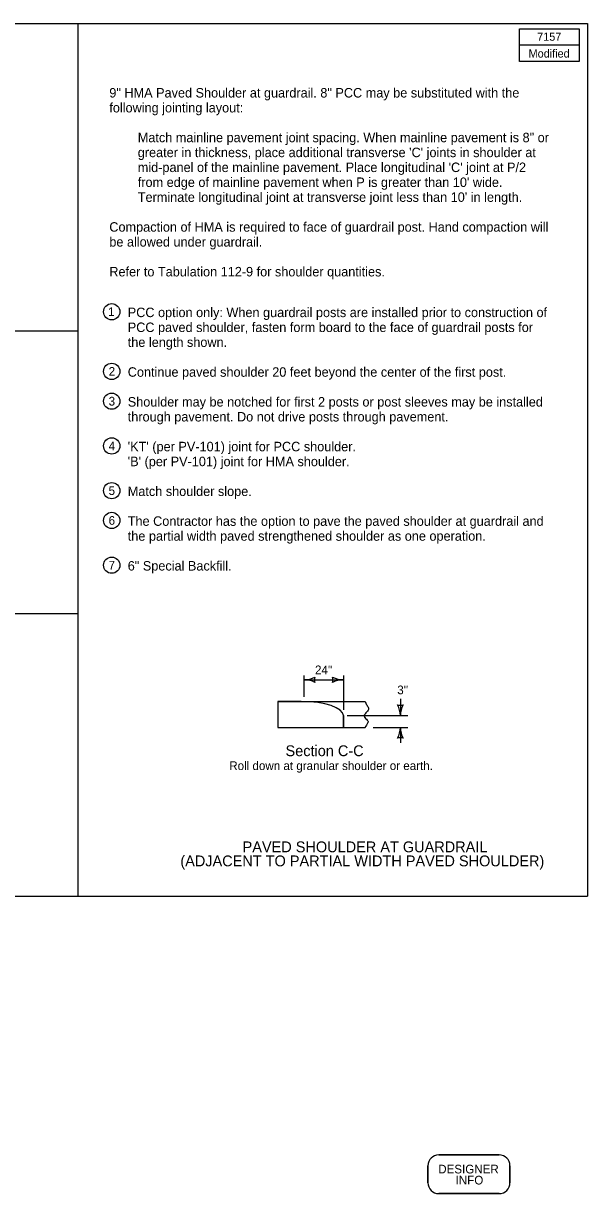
# Model space of a CAD drawing. Extents: x 10133 to 81668, y 7924 to 12229.
# Drawn here: x 12201 to 13243, y 10071 to 12229 of the extents above; entities that cross this region are included whole.
import ezdxf

# ---------------------------------------------------------------- set-up
doc = ezdxf.new("R2010")
doc.units = 0
for name, color, linetype in [('Cell', 7, 'Continuous'), ('dsnStdCells', 7, 'Continuous'), ('dsnTextFinalPlan', 7, 'Continuous'), ('Level 1', 7, 'Continuous'), ('Level 12', 7, 'Continuous'), ('Level 4', 7, 'Continuous'), ('Level 5', 7, 'Continuous'), ('Level 6', 7, 'Continuous'), ('SheetText', 7, 'Continuous')]:
    doc.layers.add(name, color=color, linetype=linetype)

msp = doc.modelspace()

# ---------------------------------------------------------------- linework, layer by layer
at = {"layer": 'Cell'}
for p, q in [((12714.3, 10978.5), (12671.2, 10978.5)), ((12671.2, 10978.5), (12671.2, 10930.5)), ((12792.1, 10930.5), (12792.1, 10952.3)), ((12671.2, 10930.5), (12792.1, 10930.5))]:
    msp.add_line(p, q, dxfattribs=at)
msp.add_lwpolyline([(12714.3, 10978.4), (12714.3, 10978.5)], dxfattribs=at)
msp.add_ellipse((12714.3, 10952.3), major_axis=(77.9, 0), ratio=0.335273, start_param=0, end_param=1.570796, dxfattribs=at)
at = {"layer": 'dsnStdCells'}
for points in [[(12968.1, 10142), (13079.5, 10142)], [(13079.5, 10142), (12968.1, 10142)], [(12948.1, 10090.6), (12948.1, 10122)], [(12948.1, 10122), (12948.1, 10090.6)], [(13099.5, 10122), (13099.5, 10090.6)], [(13099.5, 10090.6), (13099.5, 10122)], [(13079.5, 10070.6), (12968.1, 10070.6)], [(12968.1, 10070.6), (13079.5, 10070.6)]]:
    msp.add_lwpolyline(points, dxfattribs=at)
for centre, start, end in [((12968.1, 10122), 90, 180), ((12968.1, 10122), 90, 180), ((13079.5, 10122), 0, 90), ((13079.5, 10122), 0, 90), ((12968.1, 10090.6), 180, 270), ((12968.1, 10090.6), 180, 270), ((13079.5, 10090.6), 270, 0), ((13079.5, 10090.6), 270, 0)]:
    msp.add_arc(centre, 20, start, end, dxfattribs=at)
at = {"layer": 'dsnTextFinalPlan'}
for p, q in [((13242.8, 12229.2), (13242.8, 12229.2)), ((12671.2, 10978.5), (12671.2, 10930.5)), ((12671.2, 10978.5), (12714.3, 10978.4)), ((12714.3, 10978.4), (12832, 10978.4)), ((12792.1, 10952.3), (12792.1, 10930.5)), ((12671.2, 10930.5), (12792.1, 10930.5)), ((12792.1, 10930.5), (12832, 10930.5))]:
    msp.add_line(p, q, dxfattribs=at)
msp.add_ellipse((12714.3, 10952.3), major_axis=(77.9, 0), ratio=0.335273, start_param=0, end_param=1.570796, dxfattribs=at)
msp.add_spline([(12832, 10978.4), (12833.4, 10975.3), (12835.2, 10972.1), (12837.1, 10969.1), (12838.5, 10966), (12838.7, 10964.2), (12838, 10962.5), (12835.1, 10959), (12832, 10955.5), (12830.9, 10953.8), (12830.5, 10952.9), (12830.4, 10952), (12830.4, 10951.6), (12830.8, 10950.4), (12831.8, 10948.8), (12834.7, 10945.6), (12837.2, 10942.5), (12837.7, 10940.9), (12837.6, 10940.1), (12837.4, 10939.7), (12837.2, 10939.3), (12831.9, 10930.5)], degree=3, dxfattribs=at)
at = {"layer": 'Level 1'}
for p, q in [((10147.1, 12229.2), (13242.8, 12229.2)), ((13242.8, 12229.2), (13242.8, 10619.2)), ((10147.1, 10619.2), (13242.8, 10619.2))]:
    msp.add_line(p, q, dxfattribs=at)
at = {"layer": 'Level 12'}
for centre in [(12364.5, 11697.3), (12364.5, 11587.3), (12364.5, 11532.3), (12364.5, 11449.8), (12364.5, 11367.3), (12364.5, 11312.3), (12364.5, 11229.8)]:
    msp.add_circle(centre, 15, dxfattribs=at)
at = {"layer": 'Level 4'}
for p, q in [((12302.7, 10619.2), (12302.7, 12229.2)), ((12302.7, 11661.2), (10147.1, 11661.2)), ((12302.7, 11140.2), (10147.1, 11140.2))]:
    msp.add_line(p, q, dxfattribs=at)
at = {"layer": 'Level 5'}
for p, q in [((12719.6, 10987), (12719.6, 11026.4)), ((12719.6, 11018.4), (12792.1, 11018.4)), ((12792.1, 11026.4), (12792.1, 10962.9)), ((12897.2, 10983.3), (12897.2, 10952.3)), ((12798.9, 10952.3), (12911, 10952.3)), ((12846.9, 10930.5), (12911, 10930.5)), ((12897.2, 10930.5), (12897.2, 10901.9))]:
    msp.add_line(p, q, dxfattribs=at)
for centre, radius, start, end in [((12719.6, 11060.9), 42.5, 270, 298.0725), ((12719.6, 10975.9), 42.5, 61.9275, 90), ((12755.2, 11018.4), 16.4, 162.2666, 197.7334), ((12756.5, 11018.4), 16.4, 342.2666, 17.7334), ((12792.1, 11060.9), 42.5, 241.9275, 270), ((12792.1, 10975.9), 42.5, 90, 118.0725), ((12897.2, 10988), 16.4, 252.2666, 287.7334), ((12854.7, 10952.3), 42.5, 0, 28.0725), ((12939.7, 10952.3), 42.5, 151.9275, 180), ((12854.7, 10930.5), 42.5, 331.9275, 360), ((12939.7, 10930.5), 42.5, 180, 208.0725), ((12897.2, 10894.9), 16.4, 72.2666, 107.7334)]:
    msp.add_arc(centre, radius, start, end, dxfattribs=at)
at = {"layer": 'SheetText'}
msp.add_lwpolyline([(13227.1, 12219.2), (13227.1, 12159.2), (13117.1, 12159.2), (13117.1, 12219.2), (13227.1, 12219.2), (13227.1, 12189.2), (13117.1, 12189.2)], dxfattribs=at)

# ---------------------------------------------------------------- texts
at = {"layer": 'dsnStdCells'}
for s, p in [('DESIGNER', (12967.1, 10107.8)), ('INFO', (12999.2, 10087.4))]:
    msp.add_text(s, height=16, dxfattribs=at).set_placement(p)
at = {"layer": 'Level 12'}
for s, height, p in [('9" HMA Paved Shoulder at guardrail. 8" PCC may be substituted with the', 17.5, (12360.1, 12092.5)), ('following jointing layout:', 17.5, (12360.1, 12065)), ('Match mainline pavement joint spacing. When mainline pavement is 8" or ', 17.5, (12412.6, 12010)), ("greater in thickness, place additional transverse 'C' joints in shoulder at ", 17.5, (12412.6, 11982.5)), ("mid-panel of the mainline pavement. Place longitudinal 'C' joint at P/2 ", 17.5, (12412.6, 11955)), ("from edge of mainline pavement when P is greater than 10' wide. ", 17.5, (12412.6, 11927.5)), ("Terminate longitudinal joint at transverse joint less than 10' in length.", 17.5, (12412.6, 11900)), ('Compaction of HMA is required to face of guardrail post. Hand compaction will ', 17.5, (12360.1, 11845)), ('be allowed under guardrail. ', 17.5, (12360.1, 11817.5)), ('Refer to Tabulation 112-9 for shoulder quantities.', 17.5, (12360.1, 11762.5)), ('1', 16, (12357.7, 11689.3)), ('PCC option only: When guardrail posts are installed prior to construction of ', 17.5, (12394.1, 11687.4)), ('PCC paved shoulder, fasten form board to the face of guardrail posts for ', 17.5, (12394.1, 11659.9)), ('the length shown.', 17.5, (12394.1, 11632.4)), ('2', 16, (12358.9, 11579.3)), ('Continue paved shoulder 20 feet beyond the center of the first post.', 17.5, (12394.1, 11577.4)), ('3', 16, (12358.8, 11524.3)), ('Shoulder may be notched for first 2 posts or post sleeves may be installed ', 17.5, (12394.1, 11522.4)), ('through pavement. Do not drive posts through pavement.', 17.5, (12394.1, 11494.9)), ('4', 16, (12358.9, 11441.8)), ("'KT' (per PV-101) joint for PCC shoulder.", 17.5, (12394.1, 11439.9)), ("'B' (per PV-101) joint for HMA shoulder.", 17.5, (12394.1, 11412.4)), ('5', 16, (12358.8, 11359.3)), ('Match shoulder slope.', 17.5, (12394.1, 11357.4)), ('6', 16, (12358.8, 11304.3)), ('The Contractor has the option to pave the paved shoulder at guardrail and ', 17.5, (12394.1, 11302.4)), ('the partial width paved strengthened shoulder as one operation.', 17.5, (12394.1, 11274.9)), ('7', 16, (12358.8, 11221.8)), ('6" Special Backfill.', 17.5, (12394.1, 11219.9))]:
    msp.add_text(s, height=height, dxfattribs=at).set_placement(p)
at = {"layer": 'Level 5'}
for s, p in [("24''", (12739.7, 11028.7)), ("3'' ", (12891.5, 10991.7))]:
    msp.add_text(s, height=16, dxfattribs=at).set_placement(p)
at = {"layer": 'Level 6'}
for s, height, p in [('Section C-C', 20, (12685.3, 10877.5)), ('Roll down at granular shoulder or earth.', 16, (12581.5, 10851.9)), ('PAVED SHOULDER AT GUARDRAIL', 20, (12606.1, 10700.2)), ('(ADJACENT TO PARTIAL WIDTH PAVED SHOULDER)', 20, (12491.2, 10674.3))]:
    msp.add_text(s, height=height, dxfattribs=at).set_placement(p)
at = {"layer": 'SheetText'}
for s, p in [('7157', (13149.7, 12197.2)), ('Modified', (13133.9, 12166.2))]:
    msp.add_text(s, height=15, dxfattribs=at).set_placement(p)

doc.saveas('drawing.dxf')
